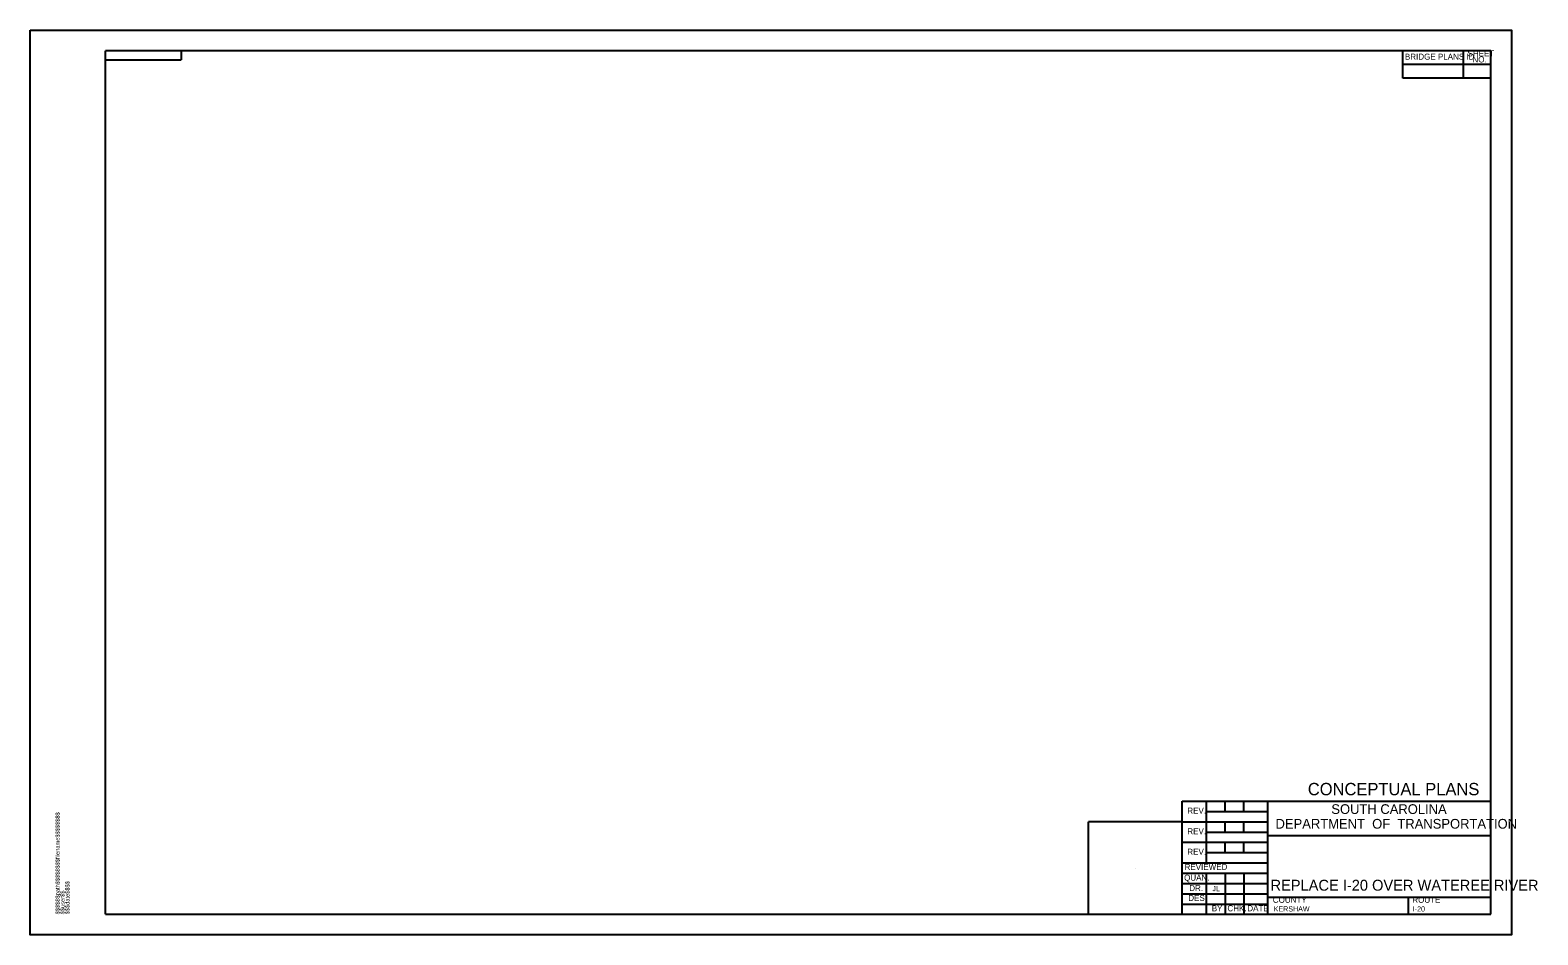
# Model space of a CAD drawing. Extents: x -1.4 to 35.2, y 0.5 to 22.5.
import ezdxf

# ---------------------------------------------------------------- set-up
doc = ezdxf.new("R2010")
doc.units = 0
for name, color, linetype in [('BR_BORDER LINES', 7, 'Continuous'), ('BR_TABLE LINES', 7, 'Continuous'), ('BR_TEXT', 7, 'Continuous'), ('Default', 7, 'Continuous'), ('RD_SHT_IplotShp', 7, 'Continuous')]:
    doc.layers.add(name, color=color, linetype=linetype)

msp = doc.modelspace()

# ---------------------------------------------------------------- linework, layer by layer
at = {"layer": 'BR_BORDER LINES'}
for p, q in [((0.43, 0.998), (0.43, 21.998)), ((34.097, 21.998), (0.43, 21.998)), ((2.264, 21.998), (2.264, 21.772)), ((31.957, 21.331), (31.957, 21.998)), ((33.263, 21.998), (33.263, 21.998)), ((33.437, 21.331), (33.437, 21.998)), ((33.679, 21.998), (33.679, 21.998)), ((34.097, 0.998), (34.097, 21.998)), ((0.43, 21.772), (2.264, 21.772)), ((31.957, 21.668), (34.097, 21.668)), ((34.097, 21.331), (31.957, 21.331)), ((26.597, 0.998), (26.597, 3.748)), ((26.597, 3.748), (34.097, 3.748)), ((27.18, 3.748), (27.18, 2.248)), ((27.639, 3.498), (27.639, 3.748)), ((28.097, 3.498), (28.097, 3.748)), ((28.68, 0.998), (28.68, 3.748)), ((27.18, 3.498), (28.68, 3.498)), ((26.597, 3.248), (24.322, 3.248)), ((24.322, 0.998), (24.322, 3.248)), ((26.597, 3.248), (28.68, 3.248)), ((27.18, 2.998), (28.68, 2.998)), ((27.639, 2.998), (27.639, 3.248)), ((28.097, 2.998), (28.097, 3.248)), ((26.597, 2.748), (28.68, 2.748)), ((27.639, 2.498), (27.639, 2.748)), ((28.097, 2.498), (28.097, 2.748)), ((28.68, 2.914), (34.097, 2.914)), ((26.597, 2.248), (28.68, 2.248)), ((27.18, 2.498), (28.68, 2.498)), ((26.597, 1.998), (28.68, 1.998)), ((27.18, 1.998), (27.18, 0.998)), ((27.639, 1.998), (27.639, 0.998)), ((28.097, 1.998), (28.097, 0.998)), ((26.597, 1.748), (28.68, 1.748)), ((26.597, 1.498), (28.68, 1.498)), ((26.597, 1.248), (28.68, 1.248)), ((28.68, 1.414), (34.097, 1.414)), ((32.097, 0.998), (32.097, 1.414)), ((0.43, 0.998), (34.097, 0.998))]:
    msp.add_line(p, q, dxfattribs=at)
at = {"layer": 'BR_TABLE LINES'}
msp.add_line((25.472, 2.123), (25.472, 2.123), dxfattribs=at)
at = {"layer": 'RD_SHT_IplotShp'}
msp.add_lwpolyline([(-1.403, 22.498), (34.597, 22.498), (34.597, 0.498), (-1.403, 0.498)], close=True, dxfattribs=at)

# ---------------------------------------------------------------- texts
at = {"layer": 'BR_TEXT'}
for s, height, p in [('SHEET', 0.1458, (33.53, 21.859)), ('BRIDGE PLANS ID', 0.14583, (32.009, 21.78)), ('NO.', 0.1458, (33.651, 21.712)), ('SOUTH CAROLINA', 0.23585, (30.221, 3.438)), ('REV.', 0.1458, (26.721, 3.445)), ('DEPARTMENT  OF  TRANSPORTATION', 0.23585, (28.865, 3.081)), ('REV.', 0.1458, (26.721, 2.945)), ('REV.', 0.1458, (26.721, 2.445)), ('REVIEWED', 0.1458, (26.654, 2.078)), ('QUAN.', 0.1458, (26.643, 1.815)), ('REPLACE I-20 OVER WATEREE RIVER', 0.26563, (28.743, 1.572)), ('DES.', 0.1458, (26.744, 1.322)), ('DR.', 0.1458, (26.768, 1.563)), ('BY', 0.1458, (27.315, 1.071)), ('CHK.', 0.1458, (27.695, 1.071)), ('DATE', 0.1458, (28.179, 1.072)), ('COUNTY', 0.1458, (28.799, 1.277)), ('KERSHAW', 0.125, (28.82, 1.066)), ('ROUTE', 0.1458, (32.19, 1.277)), ('I-20', 0.125, (32.2, 1.066))]:
    msp.add_text(s, height=height, dxfattribs=at).set_placement(p)
for s, height, rotation, p in [('CONCEPTUAL PLANS', 0.3, 0, (29.649, 3.893)), ('JL', 0.125, 360, (27.331, 1.56))]:
    msp.add_text(s, height=height, rotation=rotation, dxfattribs=at).set_placement(p)
at = {"layer": 'Default'}
for s, p in [('$$$$$$path$$$$$$$$filename$$$$$$$$', (-0.687, 0.998)), ('$$user$$', (-0.567, 0.998)), ('$$$date$$$$', (-0.447, 0.998))]:
    msp.add_text(s, height=0.1, rotation=90, dxfattribs=at).set_placement(p)

doc.saveas('drawing.dxf')
